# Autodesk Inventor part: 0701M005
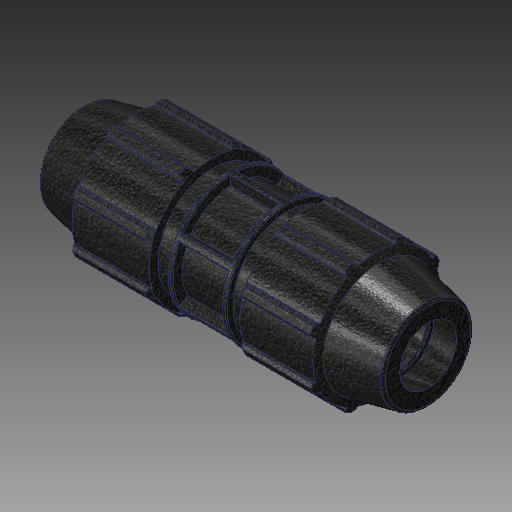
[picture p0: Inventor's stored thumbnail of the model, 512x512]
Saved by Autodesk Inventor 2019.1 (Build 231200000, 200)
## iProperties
Created: 2017-02
Part Number: 0701M005
Material: PVC-Piping
Description: PLASSON COUPLER 1/2'' - 20mm
Document SubType Name: Modeling
Designer: KIM
Mass: 92.6774 g
Surface Area: 199.44 cm^2
Volume: 66.1981 cm^3
Density: 1.4 g/cm^3
Appearance: PTFE
Author: KIM
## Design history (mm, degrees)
derived "0701M.ipt"
feature "Solid1::0701M.ipt"
tag "TaggingFeature1"
body "Solid1"
other parameters: "d4" = 10.07533, "d5" = 17.272, "d7" = 48.006, "d8" = 36.0045, "d9" = 17.272, "d11" = 1.7272, "d12" = 38.4048, "d13" = 120 deg, "d14" = 31.8, "d15" = 12 deg, "d16" = 43.2054, "d18" = 1.06, "d19" = 35 deg, "d20" = 17.5 deg, "d21" = 44.64558, "d23" = 0, "d25" = 360 deg, "d27" = 0.96012, "d33" = 0.424, "d34" = 2.4003, "d36" = 0, "d37" = 0.424, "d38" = 0.424, "d40" = 360 deg, "d42" = 26.59888, "d43" = 1.44018, "d46" = 0.636, "d50" = 16.96, "d51" = 57.912, "d53" = 1.7272, "d54" = 26.59888, "d55" = 120 deg, "d56" = 12 deg, "d57" = 10.07533, "d58" = 120.904, "d59" = 17.272, "d63" = 17.272, "d68" = 0, "d69" = 0.424, "d70" = 1.06, "d72" = 0, "d73" = 1.44018, "d77" = 57.912, "d78" = 21.2, "d_" = 21.2, "E_" = 48.006, "H_" = 120.904, "l_" = 57.912
